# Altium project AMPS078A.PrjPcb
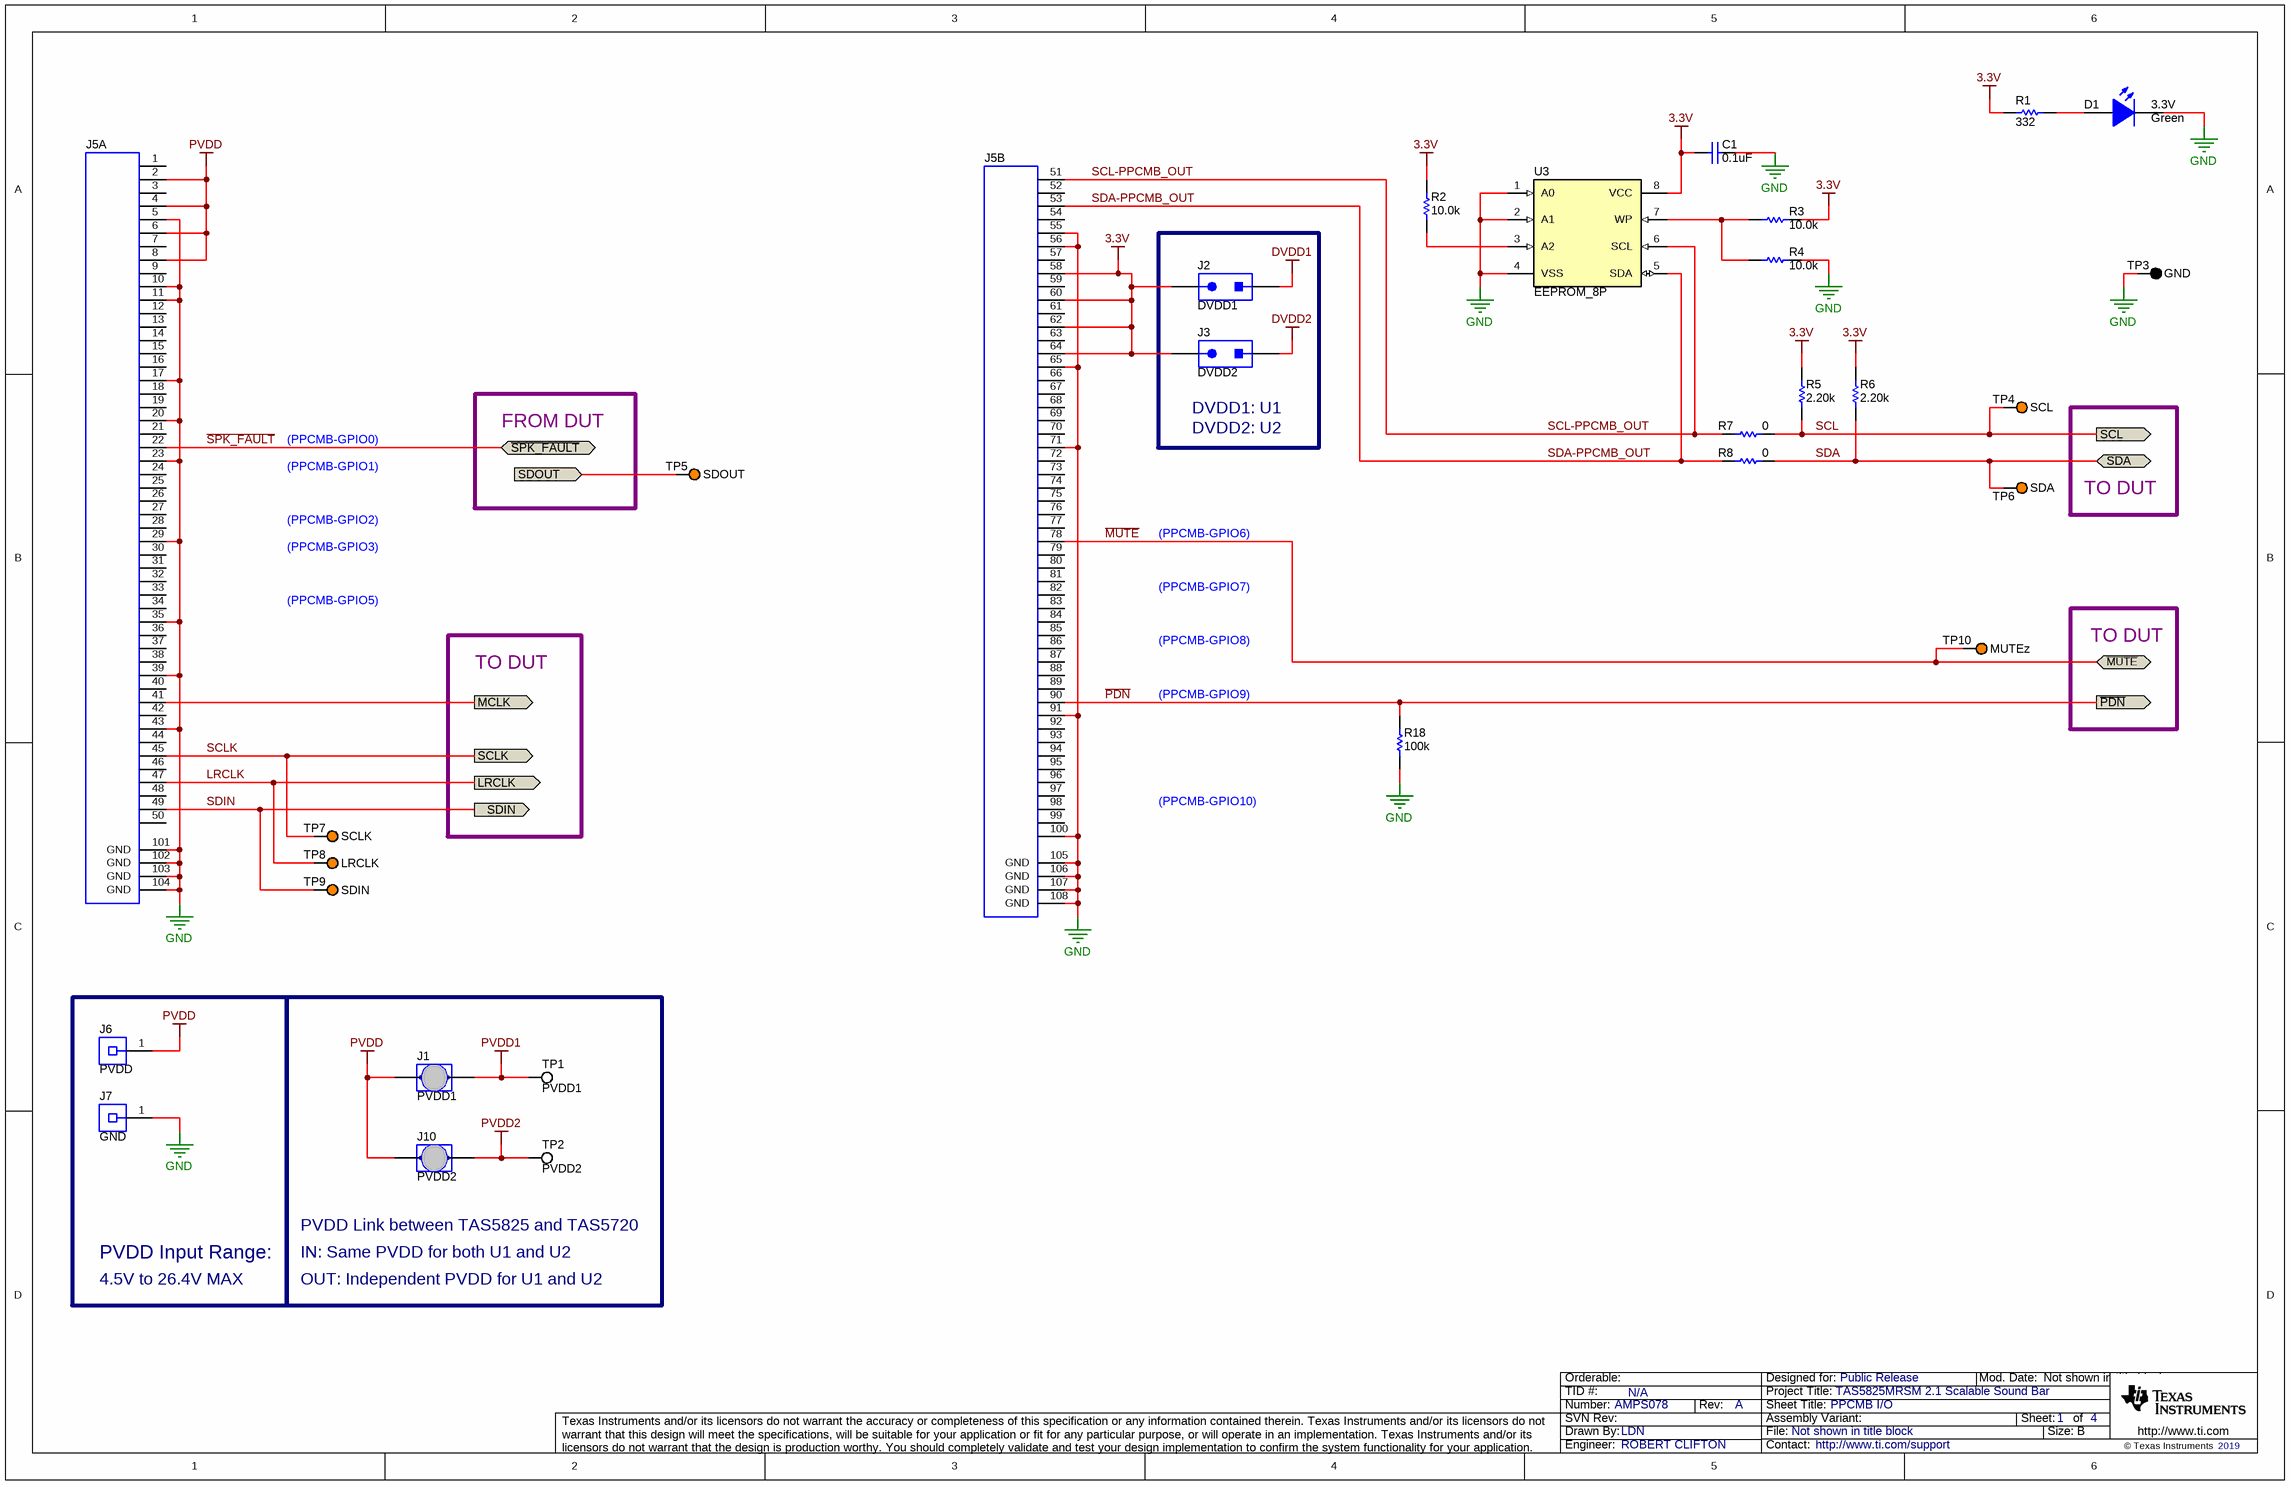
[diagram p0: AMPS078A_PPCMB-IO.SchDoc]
CopyrightYear: 2019; PCB_Layout: LDN; PCB_Rev: A; PRJ_Customer: Public Release; PRJ_Engineer: ROBERT CLIFTON; PRJ_Number: AMPS078; PRJ_Title: TAS5825MRSM 2.1 Scalable Sound Bar; SCH_Rev: A; TechSupport: http://www.ti.com/support; TID: N/A
4 sheets, 114 parts. Net scope: flat (ports and power ports of the same name join across sheets).
Board file: AMPS078A_PCB.PcbDoc
Sheets:
  AMPS078A_PPCMB-IO.SchDoc
  AMPS078A_TAS5720MRSM.SchDoc
  AMPS078A_TAS5825MRSM.SchDoc
  AMPS078A_Hardware.SchDoc

## Sheet AMPS078A_PPCMB-IO.SchDoc: PPCMB I/O
size 431 x 279 mm; Date: Not shown in title block; ApprovedBy: Not shown in title block; CheckedBy: Not shown in title block; Author: Not shown in title block; CompanyName: Not shown in title block; DrawnBy: LDN; Engineer: Not shown in title block; Organization: Not shown in title block; Address1: Not shown in title block; Address2: Not shown in title block; Address3: Not shown in title block; Address4: Not shown in title block; DocumentNumber: 1; Revision: Use project parameter SCH_Rev; SheetNumber: 1; SheetTotal: 4; PageSetup: Record=PageOptions¦CenterHorizontal=True¦CenterVertical=True¦PrintScale=1.00¦XCorrection=1.00¦YCorrection=1.00¦PrintKind=0¦BorderSize=5000000¦LeftOffset=0¦BottomOffset=0¦Orientation=2¦PaperLength=1000¦PaperWidth=1000¦Scale=100¦PaperSource=15¦PrintQuality=600¦MediaType=1¦DitherType=10¦PaperKind=Letter¦PrintScaleMode=1

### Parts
C1  ValueDisplayed: 0.1uF  [0603L]  (hidden comment: GRM188R71H104KA93D)
D1  3.3V  value Green  [LTST-C170KGKT_Green]
J1  PVDD1  [HARWIN_S1911-46R]
J2  DVDD1  [Sullins_PBC02SAAN]
J3  DVDD2  [Sullins_PBC02SAAN]
J5  QTS-050-01-F-D-A  [CONN_QTS-050-01-F-D-A]  (value not drawn)  (parts A,B of 2)
J6  PVDD  [Keystone_7006]
J7  GND  [Keystone_7007]
J10  PVDD2  [HARWIN_S1911-46R]
R1  ValueDisplayed: 332  [0402L]  (hidden comment: Resistor)
R2  ValueDisplayed: 10.0k  [0402L]  (hidden comment: Resistor)
R3  ValueDisplayed: 10.0k  [0402L]  (hidden comment: Resistor)
R4  ValueDisplayed: 10.0k  [0402L]  (hidden comment: Resistor)
R5  ValueDisplayed: 2.20k  [0402L]  (hidden comment: Resistor)
R6  ValueDisplayed: 2.20k  [0402L]  (hidden comment: Resistor)
R7  ValueDisplayed: 0  [0603L]  (hidden comment: Resistor)
R8  ValueDisplayed: 0  [0603L]  (hidden comment: Resistor)
R18  ValueDisplayed: 100k  [0402L]  (hidden comment: ERJ-2RKF1003X)
TP1  PVDD1  [Testpoint_Keystone_Compact]
TP2  PVDD2  [Testpoint_Keystone_Compact]
TP3  GND  [Keystone5001]
TP4  SCL  [Keystone5003]
TP5  SDOUT  [Keystone5003]
TP6  SDA  [Keystone5003]
TP7  SCLK  [Keystone5003]
TP8  LRCLK  [Keystone5003]
TP9  SDIN  [Keystone5003]
TP10  MUTEz  [Keystone5003]
U3  EEPROM_8P  [TSSOP-8]

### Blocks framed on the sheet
PVDD Input Range:: J6 J7

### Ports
LRCLK (out), MCLK (out), SCL (out), SCLK (out), SDA (bidir), SDIN (out), SDOUT (in), ~{MUTE} (bidir), ~{PDN} (out), ~{SPK_FAULT} (bidir)

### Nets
3.3V: C1.1 J2.2 J3.2 J5.58 J5.60 J5.62 J5.64 R1.2 R2.2 R3.1 R5.2 R6.2 U3.8(VCC)
DVDD1: J2.1
DVDD2: J3.1
GND: C1.2 D1.2(K) J5.5 J5.10 J5.11 J5.17 J5.20 J5.23 J5.29 J5.35 J5.39 J5.43 J5.55 J5.56 J5.65 J5.71 J5.91 J5.100 J5.101(GND) J5.102(GND) J5.103(GND) J5.104(GND) J5.105(GND) J5.106(GND) J5.107(GND) J5.108(GND) J7.1 R4.1 R18.1 TP3.1 U3.1(A0) U3.2(A1) U3.4(VSS)
PVDD: J1.1 J5.2 J5.4 J5.6 J5.8 J6.1 J10.1
PVDD1: J1.2 TP1.1
PVDD2: J10.2 TP2.1
~{MUTE}: J5.78 TP10.1 ; port ~{MUTE}
~{PDN}: J5.90 R18.2 ; port ~{PDN}
~{SPK_FAULT}: J5.22 ; port ~{SPK_FAULT}
LRCLK: J5.47 TP8.1 ; port LRCLK
MCLK: J5.41 ; port MCLK
SCL: R5.1 R7.1 TP4.1 ; port SCL
SCL-PPCMB_OUT: J5.51 R7.2 U3.6(SCL)
SCLK: J5.45 TP7.1 ; port SCLK
SDA: R6.1 R8.1 TP6.1 ; port SDA
SDA-PPCMB_OUT: J5.53 R8.2 U3.5(SDA)
SDIN: J5.49 TP9.1 ; port SDIN
SDOUT: TP5.1 ; port SDOUT
NetD1_1: D1.1(A) R1.1
NetR2_1: R2.1 U3.3(A2)
NetR3_2: R3.2 R4.2 U3.7(WP)

Not connected (* = marked no-connect by the designer): J5 1 3 7 9 12 13 14 15 16 18 19 21 24 25 26 27 28 30 31 32 33 34 36 37 38 40 42 44 46 48 50 52(2) 54(4) 57(7) 59(9) 61(11) 63(13) 66(16) 67(17) 68(18) 69(19) 70(20) 72(22) 73(23) 74(24) 75(25) 76(26) 77(27) 79(29) 80(30) 81(31) 82(32) 83(33) 84(34) 85(35) 86(36) 87(37) 88(38) 89(39) 92(42) 93(43) 94(44) 95(45) 96(46) 97(47) 98(48) 99(49)

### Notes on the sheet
- FROM DUT
- (near J3) DVDD1: U1
- DVDD2: U2
- (PPCMB-GPIO0)
- (PPCMB-GPIO1)
- TO DUT
- (PPCMB-GPIO3)
- (PPCMB-GPIO2)
- (PPCMB-GPIO6)
- (PPCMB-GPIO5)
- (PPCMB-GPIO7)
- (PPCMB-GPIO8)
- (PPCMB-GPIO9)
- (PPCMB-GPIO10)
- PVDD Link between TAS5825 and TAS5720
- 4.5V to 26.4V MAX
- IN: Same PVDD for both U1 and U2
- OUT: Independent PVDD for U1 and U2

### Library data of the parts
C1 = CMP-0007434-4: CAP, CERM, 0.1 uF, 50 V, +/- 10%, X7R, 0603; Manufacturer: MuRata; TaMin_C: -55°C; Polarized: N; SizeAreaWB_mm2: 4.68; Value1: Unknown; U/M: EA; Value: 0.1uF; TaMax_C: 125°C; SizeZ_mm: 1; SizeX_mm: 1.6; SizeY_mm: 0.8; Cap_Case: 0603; Value2: 50V; SizeArea_mm2: 1.28; CompType: Capacitor; Cap_F: 100nF; AEC Category: Q200
D1 = CMP-0002888-1: LED, Green, SMD; Manufacturer: Lite-On; PartNumber: LTST-C170KGKT; Type: AlInGaP; Vf_V: 2V; Io_A: 20mA; Value1: W; U/M: EA
J1 J10 = CMP-0075020-1: JUMPER TIN SMD; Manufacturer: Harwin; PartNumber: S1911-46R; CNHeader: False; Green_Lifecycle: Active; Green_REACh: Passed; CompType: Jumper SMT
J2 J3 = CMP-0054566-1: Header, 100mil, 2x1, Gold, TH; Manufacturer: Sullins Connector Solutions; PartNumber: PBC02SAAN; CNHeader: TRUE; Current_A: 3A; Green_Lifecycle: Active; Shrouded: N; Gender: Male; Green_REACh: Passed; Voltage_V: 1.8kV; Row_Count: 1; Pitch_mm: 2.54; CT: FALSE; Cert_UL: Y
J5 = CMP-0055971-1: Connector, 100 Pos. 0.635mm, SMT; Manufacturer: Samtec; CNHeader: FALSE; Green_Lifecycle: Active; Green_REACh: Passed
J6 = CMP-0055127-1: Binding Post, RED, TH; Manufacturer: Keystone; PartNumber: 7006; CNHeader: FALSE; Green_Lifecycle: Active; Green_REACh: Passed; CompType: Connector
J7 = CMP-0055128-1: Binding Post, BLACK, TH; Manufacturer: Keystone; PartNumber: 7007; CNHeader: FALSE; Green_Lifecycle: Active; Green_REACh: Passed; CompType: Connector
R1 = CMP-0026297-2: RES, 332, 1%, 0.063 W, AEC-Q200 Grade 0, 0402; PartNumber: CRCW0402332RFKED; Manufacturer: Vishay-Dale; Value: 332; Value_Code: 332R; Power_W: 63mW; Value2: 0.063W; VDC_V: 50V; TempCo: 100 ppm/C; EIA_Code: E96; AEC Category: Q200; AEC Qualified: Y; AEC Grade: 0; SizeArea_mm2: 0.5; SizeX_mm: 1; SizeZ_mm: 0.6
R2-R4 = CMP-0025958-3: RES, 10.0 k, 1%, 0.063 W, AEC-Q200 Grade 0, 0402; PartNumber: CRCW040210K0FKED; Manufacturer: Vishay-Dale; Value: 10.0k; Res_ohm: 10k; Value_Code: 10k0; Power_W: 63mW; Value2: 0.063W; VDC_V: 50V; TempCo: 100 ppm/C; EIA_Code: E96; AEC Category: Q200; AEC Qualified: Y; AEC Grade: 0; SizeArea_mm2: 0.5; SizeX_mm: 1; SizeZ_mm: 0.6
R5 R6 = CMP-0026231-2: RES, 2.20 k, 1%, 0.063 W, AEC-Q200 Grade 0, 0402; PartNumber: CRCW04022K20FKED; Manufacturer: Vishay-Dale; Value: 2.20k; Res_ohm: 2.2k; Value_Code: 2k20; Power_W: 63mW; Value2: 0.063W; TempCo: 100 ppm/C; AEC Category: Q200; AEC Qualified: Y; AEC Grade: 0; SizeArea_mm2: 0.5; SizeX_mm: 1; SizeZ_mm: 0.6
R7 R8 = CMP-0025697-4: RES, 0, 5%, 0.1 W, AEC-Q200 Grade 0, 0603; PartNumber: CRCW06030000Z0EA; Manufacturer: Vishay-Dale; Value: 0; Value_Code: 0000; Power_W: 100mW; Value2: 0.1W; VDC_V: 75V; TempCo: 200 ppm/C; EIA_Code: E24; AEC Category: Q200; AEC Qualified: Y; SizeArea_mm2: 1.28; SizeX_mm: 1.6; SizeY_mm: 0.8; SizeZ_mm: 1
R18 = CMP-0026659-1: RES, 100 k, 1%, 0.1 W, 0402; Manufacturer: Panasonic; Power_W: 100mW; TempCo: 100 ppm/C; U/M: EA; Value: 100k; EIA_Code: E96; SizeX_mm: 1; SizeY_mm: 0.5; SizeZ_mm: 0.6; Value2: 0.1W; CompType: Resistor; VDC_V: 50V; AEC Category: Q200
TP1 TP2 = CMP-0055153-1: Test Point, Compact, SMT; Manufacturer: Keystone; PartNumber: 5016; CNHeader: FALSE; Green_Lifecycle: Active; Green_REACh: Passed; CT: TRUE
TP3 = CMP-0055138-1: Test Point, Miniature, Black, TH; Manufacturer: Keystone; ContactFinish: Silver; CNHeader: FALSE; CT: TRUE; Green_Lifecycle: Active; Green_REACh: Passed
TP4-TP9 = CMP-0055140-1: Test Point, Miniature, Orange, TH; PartNumber: 5003; Manufacturer: Keystone; ContactFinish: Silver; CNHeader: FALSE; CT: TRUE; Green_Lifecycle: Active; Green_REACh: Passed
TP10 = CMP-0055140-1: Test Point, Miniature, Orange, TH; Manufacturer: Keystone; PartNumber: 5003; CNHeader: FALSE; Green_Lifecycle: Active; Green_REACh: Passed; ContactFinish: Silver; CT: TRUE
U3 = CMP-0005242-2: EEPROM, 512KBIT, 400KHZ, 8TSSOP; PartNumber: 24LC512-I/ST; Manufacturer: Microchip; SizeAreaWB_mm2: 42; SizeArea_mm2: 19.2; SizeX_mm: 6.4; SizeY_mm: 3; SizeZ_mm: 1.2

## Sheet AMPS078A_TAS5720MRSM.SchDoc: TAS5720MRSM I/O
size 323 x 209 mm; Date: Not shown in title block; ApprovedBy: Not shown in title block; CheckedBy: Not shown in title block; Author: Not shown in title block; CompanyName: Not shown in title block; DrawnBy: LDN; Engineer: Not shown in title block; Organization: Not shown in title block; Address1: Not shown in title block; Address2: Not shown in title block; Address3: Not shown in title block; Address4: Not shown in title block; DocumentNumber: 2; Revision: Use project parameter SCH_Rev; SheetNumber: 2; SheetTotal: 4; PageSetup: Record=PageOptions¦CenterHorizontal=True¦CenterVertical=True¦PrintScale=1.00¦XCorrection=1.00¦YCorrection=1.00¦PrintKind=0¦BorderSize=5000000¦LeftOffset=0¦BottomOffset=0¦Orientation=2¦PaperLength=1000¦PaperWidth=1000¦Scale=100¦PaperSource=15¦PrintQuality=600¦MediaType=1¦DitherType=10¦PaperKind=Letter¦PrintScaleMode=1
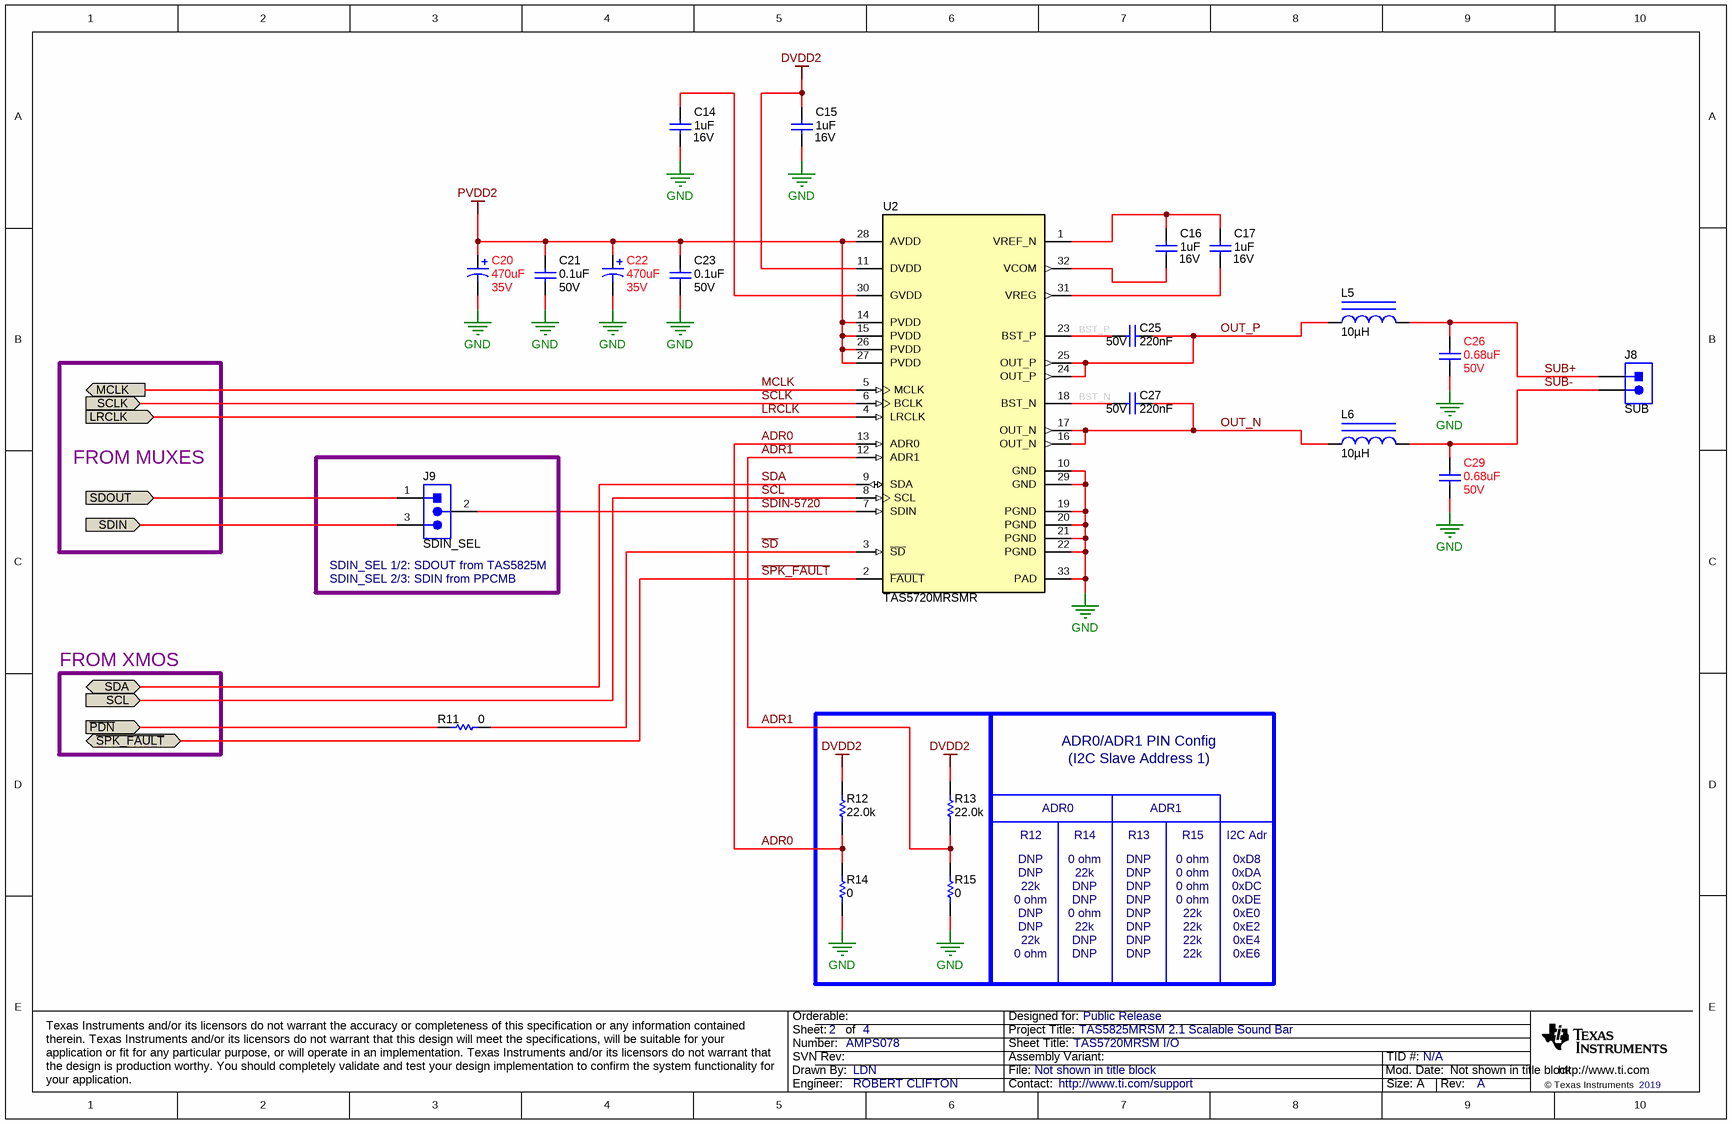
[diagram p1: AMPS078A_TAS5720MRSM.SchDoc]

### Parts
C14  VDC_V: 16V  ValueDisplayed: 1uF  [0603L]  (hidden comment: GRM188R71C105KA12D)
C15  VDC_V: 16V  ValueDisplayed: 1uF  [0603L]  (hidden comment: GRM188R71C105KA12D)
C16  VDC_V: 16V  ValueDisplayed: 1uF  [0603L]  (hidden comment: GRM188R71C105KA12D)
C17  VDC_V: 16V  ValueDisplayed: 1uF  [0603L]  (hidden comment: GRM188R71C105KA12D)
C20  VDC_V: 35V  ValueDisplayed: 470uF  [CAPSMT_62_KE0]  (hidden comment: +)
C21  VDC_V: 50V  ValueDisplayed: 0.1uF  [0603L]  (hidden comment: GRM188R71H104KA93D)
C22  VDC_V: 35V  ValueDisplayed: 470uF  [CAPSMT_62_KE0]  (hidden comment: +)
C23  VDC_V: 50V  ValueDisplayed: 0.1uF  [0603L]  (hidden comment: GRM188R71H104KA93D)
C25  Cap_F: 220nF  VDC_V: 50V  [0603L]  (hidden comment: GCM188R71H224KA64D)
C26  VDC_V: 50V  ValueDisplayed: 0.68uF  [0805_HV1]  (hidden comment: C2012X7R1H684M125AB)
C27  Cap_F: 220nF  VDC_V: 50V  [0603L]  (hidden comment: GCM188R71H224KA64D)
C29  VDC_V: 50V  ValueDisplayed: 0.68uF  [0805_HV1]  (hidden comment: C2012X7R1H684M125AB)
J8  SUB  [JST_B2PS-VH]
J9  SDIN_SEL  [PBC03SAAN]
L5  ValueDisplayed: 10µH  [DEM10050C]  (hidden comment: 1274AS-H-100M=P3)
L6  ValueDisplayed: 10µH  [DEM10050C]  (hidden comment: 1274AS-H-100M=P3)
R11  ValueDisplayed: 0  [0603L]  (hidden comment: CRCW06030000Z0EA)
R12  ValueDisplayed: 22.0k  [0603L]  (hidden comment: DNP)
R13  ValueDisplayed: 22.0k  [0603L]  (hidden comment: DNP)
R14  ValueDisplayed: 0  [0603L]  (hidden comment: CRCW06030000Z0EA)
R15  ValueDisplayed: 0  [0603L]  (hidden comment: CRCW06030000Z0EA)
U2  TAS5720MRSMR  [RSM0032B]

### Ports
LRCLK (in), MCLK (out), SCL (in), SCLK (in), SDA (bidir), SDIN (in), SDOUT (in), ~{PDN} (in), ~{SPK_FAULT} (bidir)

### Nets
DVDD2: C15.1 R12.2 R13.2 U2.11(DVDD)
GND: C14.2 C15.2 C20.2(-) C21.2 C22.2(-) C23.2 C26.2 C29.2 R14.1 R15.1 U2.10(GND) U2.19(PGND) U2.20(PGND) U2.21(PGND) U2.22(PGND) U2.29(GND) U2.33(PAD)
PVDD2: C20.1(+) C21.1 C22.1(+) C23.1 U2.14(PVDD) U2.15(PVDD) U2.26(PVDD) U2.27(PVDD) U2.28(AVDD)
~{PDN}: R11.2 ; port ~{PDN}
~{SD}: R11.1 U2.3(~{SD})
~{SPK_FAULT}: U2.2(~{FAULT}) ; port ~{SPK_FAULT}
ADR0: R12.1 R14.2 U2.13(ADR0)
ADR1: R13.1 R15.2 U2.12(ADR1)
BST_N: C27.1 U2.18(BST_N)
BST_P: C25.1 U2.23(BST_P)
LRCLK: U2.4(LRCLK) ; port LRCLK
MCLK: U2.5(MCLK) ; port MCLK
OUT_N: C27.2 L6.1 U2.16(OUT_N) U2.17(OUT_N)
OUT_P: C25.2 L5.1 U2.24(OUT_P) U2.25(OUT_P)
SCL: U2.8(SCL) ; port SCL
SCLK: U2.6(BCLK) ; port SCLK
SDA: U2.9(SDA) ; port SDA
SDIN: J9.3 ; port SDIN
SDIN-5720: J9.2 U2.7(SDIN)
SDOUT: J9.1 ; port SDOUT
SUB+: C26.1 J8.1 L5.2
SUB-: C29.1 J8.2 L6.2
NetC14_1: C14.1 U2.30(GVDD)
NetC16_1: C16.1 C17.1 U2.1(VREF_N)
NetC16_2: C16.2 U2.32(VCOM)
NetC17_2: C17.2 U2.31(VREG)

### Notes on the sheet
- FROM MUXES
- (near J9) SDIN_SEL 1/2: SDOUT from TAS5825M
- (near J9) SDIN_SEL 2/3: SDIN from PPCMB
- FROM XMOS
- ADR0/ADR1 PIN Config
- ADR0
- (I2C Slave Address 1)
- ADR1
- R12
- DNP
- R14
- 0 ohm
- 22k
- R13
- R15
- I2C Adr
- 0xD8
- 0xDA
- 0xDC
- 0xDE
- 0xE0
- 0xE2
- 0xE4
- 0xE6

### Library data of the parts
C14-C17 = CMP-0007379-4: CAP, CERM, 1 uF, 16 V, +/- 10%, X7R, 0603; Manufacturer: MuRata; TaMin_C: -55°C; ESR_ohm: 0.011; Polarized: N; SizeAreaWB_mm2: 4.68; Value1: 0.011 ohm; U/M: EA; Value: 1uF; TaMax_C: 125°C; SizeZ_mm: 1; SizeX_mm: 1.6; SizeY_mm: 0.8; Cap_Case: 0603; SizeArea_mm2: 1.28; CompType: Capacitor; Cap_F: 1µF; AEC Category: Q200
C20 C22 = CMP-0010879-1: CAP, AL, 470 uF, 35 V, +/- 20%, SMD; Manufacturer: Chemi-Con; PartNumber: EMVE350ATR471MKE0S; NewPartNumber: EMVE350ARA471MKE0S; TaMin_C: -40°C; Polarized: Y; SizeAreaWB_mm2: 225; Value1: Unknown; U/M: EA; Value: 470uF; TaMax_C: 105°C; SizeZ_mm: 13.5; SizeX_mm: 13; Cap_Case: KE0; SizeArea_mm2: 169; CompType: Capacitor; Cap_F: 470µF; IRMS_A: 5.2dA; AEC Category: Q200
C21 C23 = CMP-0007434-4: CAP, CERM, 0.1 uF, 50 V, +/- 10%, X7R, 0603; Manufacturer: MuRata; TaMin_C: -55°C; Polarized: N; SizeAreaWB_mm2: 4.68; Value1: Unknown; U/M: EA; Value: 0.1uF; TaMax_C: 125°C; SizeZ_mm: 1; SizeX_mm: 1.6; SizeY_mm: 0.8; Cap_Case: 0603; SizeArea_mm2: 1.28; CompType: Capacitor; Cap_F: 100nF; AEC Category: Q200
C25 C27 = CMP-0007145-4: CAP, CERM, 0.22 uF, 50 V, +/- 10%, X7R, AEC-Q200 Grade 1, 0603; Manufacturer: MuRata; TaMin_C: -55°C; Polarized: N; SizeAreaWB_mm2: 4.68; Value1: Unknown; U/M: EA; Value: 0.22uF; TaMax_C: 125°C; SizeZ_mm: 1; SizeX_mm: 1.6; SizeY_mm: 0.8; Cap_Case: 0603; SizeArea_mm2: 1.28; AEC Qualified: Y; AEC Category: Q200
C26 C29 = CMP-0007882-2: CAP, CERM, 0.68 uF, 50 V, +/- 20%, X7R, 0805; Manufacturer: TDK; NewPartNumber: CGA4J3X7R1H684M125AB; TaMin_C: -55°C; Polarized: N; SizeAreaWB_mm2: 6.75; Value1: Unknown; U/M: EA; Value: 0.68uF; TaMax_C: 125°C; SizeZ_mm: 1.45; SizeX_mm: 2; SizeY_mm: 1.25; Cap_Case: 0805; SizeArea_mm2: 2.5; CompType: Capacitor; Cap_F: 680nF; AEC Category: Q200
J8 = CMP-0074989-1: Header (friction lock), 3.96mm, 2x1, Tin, R/A, TH; Manufacturer: JST Manufacturing; PartNumber: B2PS-VH(LF)(SN); CNHeader: False; Green_Lifecycle: Active; Green_REACh: Passed
J9 = CMP-0002334-1: Header, 100mil, 3x1, Gold, TH; Manufacturer: Sullins Connector Solutions; CNHeader: TRUE; Green_Lifecycle: Not Set; Green_REACh: Incomplete; CT: FALSE
L5 L6 = CMP-0077807-1: Inductor, Shielded, Ferrite, 10 µH, 4.4 A, 0.0304 ohm, SMD; Manufacturer: MuRata; Isat: 6.2A @ 30% inductance drop; Irms: 4.4A @ 40C rise; SizeAreaWB_mm2: 144.0; DCR_ohm: 0.0304; Value: 10uH; Imax_A: 4.4A; SizeZ_mm: 5.0; SizeX_mm: 10.0; SizeArea_mm2: 100.0; AEC Qualified: N; AEC Category: Q200
R11 R14 R15 = CMP-0025697-4: RES, 0, 5%, 0.1 W, AEC-Q200 Grade 0, 0603; Manufacturer: Vishay-Dale; Power_W: 100mW; TempCo: 200 ppm/C; Value_Code: 0000; Value: 0; EIA_Code: E24; SizeX_mm: 1.6; SizeY_mm: 0.8; SizeZ_mm: 1; Value2: 0.1W; SizeArea_mm2: 1.28; CompType: Resistor; AEC Qualified: Y; VDC_V: 75V; AEC Category: Q200
R12 R13 = CMP-0022692-3: RES, 22.0 k, 1%, 0.1 W, AEC-Q200 Grade 0, 0603; Manufacturer: Panasonic; PartNumber: ERJ-3EKF2202V; Power_W: 100mW; TempCo: 100 ppm/C; Value_Code: 22k0; U/M: EA; Value: 22.0k; Res_ohm: 22k; SizeX_mm: 1.6; SizeY_mm: 0.8; SizeZ_mm: 1; Value2: 0.1W; SizeArea_mm2: 1.28; CompType: Resistor; AEC Qualified: Y; VDC_V: 50V; AEC Grade: 0; AEC Category: Q200
U2 = CMP-0075842-2: Closed Loop I2S Input Amplifier with Power Limiter, PVDDmax of 26.4V, RSM0032B (VQFN-32); Manufacturer: Texas Instruments; Alternate PartNumber: TAS5720MRSMT; SizeAreaWB_mm2: 25; SizeArea_mm2: 16; SizeZ_mm: 1; SizeY_mm: 4; CompType: IC; AEC Category: Q200; AEC Qualified: N

## Sheet AMPS078A_TAS5825MRSM.SchDoc: TAS5825MRSM I/O
size 323 x 209 mm; Date: Not shown in title block; ApprovedBy: Not shown in title block; CheckedBy: Not shown in title block; Author: Not shown in title block; CompanyName: Not shown in title block; DrawnBy: LDN; Engineer: Not shown in title block; Organization: Not shown in title block; Address1: Not shown in title block; Address2: Not shown in title block; Address3: Not shown in title block; Address4: Not shown in title block; DocumentNumber: 3; Revision: Use project parameter SCH_Rev; SheetNumber: 3; SheetTotal: 4; PageSetup: Record=PageOptions¦CenterHorizontal=True¦CenterVertical=True¦PrintScale=1.00¦XCorrection=1.00¦YCorrection=1.00¦PrintKind=0¦BorderSize=5000000¦LeftOffset=0¦BottomOffset=0¦Orientation=2¦PaperLength=1000¦PaperWidth=1000¦Scale=100¦PaperSource=15¦PrintQuality=600¦MediaType=1¦DitherType=10¦PaperKind=Letter¦PrintScaleMode=1
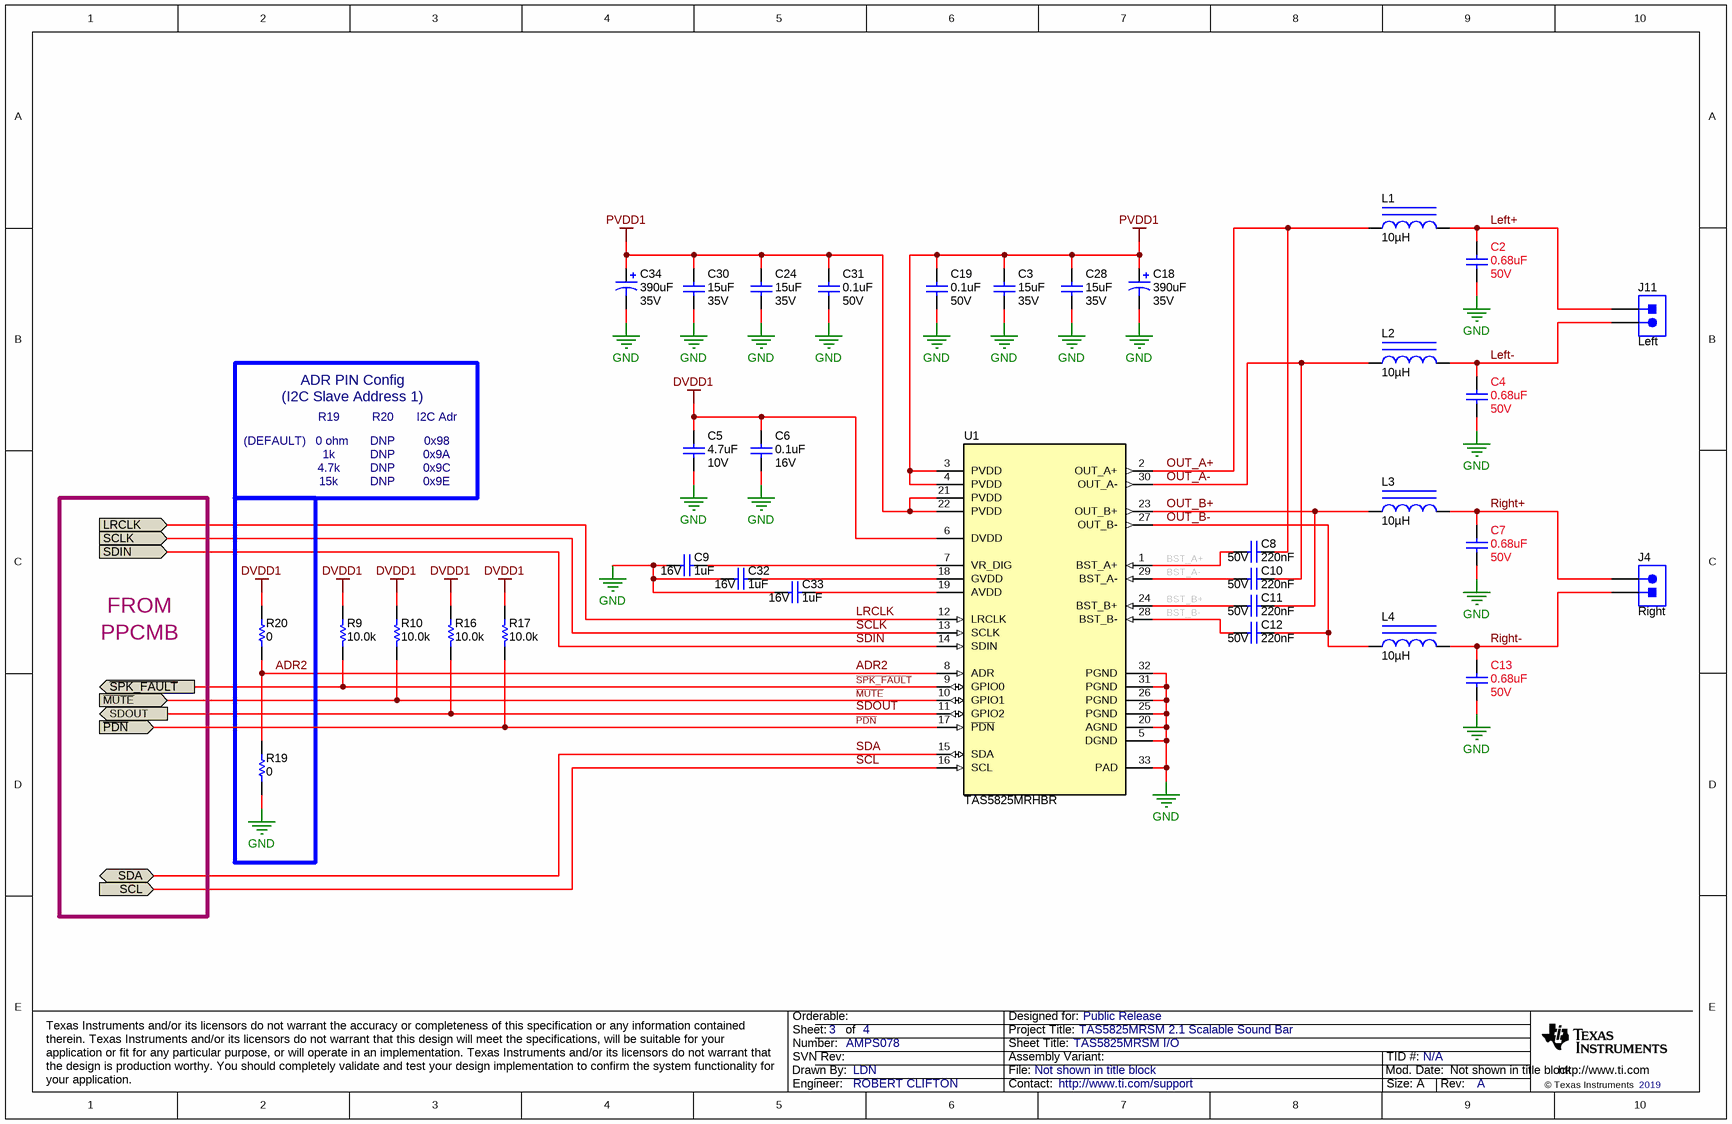
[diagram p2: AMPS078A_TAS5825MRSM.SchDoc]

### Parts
C2  VDC_V: 50V  ValueDisplayed: 0.68uF  [0805L]  (hidden comment: C0805C684K5RACTU)
C3  VDC_V: 35V  ValueDisplayed: 15uF  [0805L]  (hidden comment: C2012X5R1V156M125AC)
C4  VDC_V: 50V  ValueDisplayed: 0.68uF  [0805L]  (hidden comment: C0805C684K5RACTU)
C5  VDC_V: 10V  ValueDisplayed: 4.7uF  [0603L]  (hidden comment: C0603C475K8PACTU)
C6  VDC_V: 16V  ValueDisplayed: 0.1uF  [0603L]  (hidden comment: C0603C104K4RACTU)
C7  VDC_V: 50V  ValueDisplayed: 0.68uF  [0805L]  (hidden comment: C0805C684K5RACTU)
C8  Cap_F: 220nF  VDC_V: 50V  [0603L]  (hidden comment: GCM188R71H224KA64D)
C9  VDC_V: 16V  ValueDisplayed: 1uF  [0603L]  (hidden comment: C0603C105K4PACTU)
C10  Cap_F: 220nF  VDC_V: 50V  [0603L]  (hidden comment: GCM188R71H224KA64D)
C11  Cap_F: 220nF  VDC_V: 50V  [0603L]  (hidden comment: GCM188R71H224KA64D)
C12  Cap_F: 220nF  VDC_V: 50V  [0603L]  (hidden comment: GCM188R71H224KA64D)
C13  VDC_V: 50V  ValueDisplayed: 0.68uF  [0805L]  (hidden comment: C0805C684K5RACTU)
C18  VDC_V: 35V  ValueDisplayed: 390uF  [SM_RADIAL_10BMM]  (hidden comment: +)
C19  VDC_V: 50V  ValueDisplayed: 0.1uF  [0402L]  (hidden comment: CGA2B3X7R1H104K050BB)
C24  VDC_V: 35V  ValueDisplayed: 15uF  [0805L]  (hidden comment: C2012X5R1V156M125AC)
C28  VDC_V: 35V  ValueDisplayed: 15uF  [0805L]  (hidden comment: C2012X5R1V156M125AC)
C30  VDC_V: 35V  ValueDisplayed: 15uF  [0805L]  (hidden comment: C2012X5R1V156M125AC)
C31  VDC_V: 50V  ValueDisplayed: 0.1uF  [0402L]  (hidden comment: CGA2B3X7R1H104K050BB)
C32  VDC_V: 16V  ValueDisplayed: 1uF  [0603L]  (hidden comment: C0603C105K4PACTU)
C33  VDC_V: 16V  ValueDisplayed: 1uF  [0603L]  (hidden comment: C0603C105K4PACTU)
C34  VDC_V: 35V  ValueDisplayed: 390uF  [SM_RADIAL_10BMM]  (hidden comment: +)
J4  Right  [JST_B2PS-VH]
J11  Left  [JST_B2PS-VH]
L1  ValueDisplayed: 10µH  [DEM10050C]  (hidden comment: 1274AS-H-100M=P3)
L2  ValueDisplayed: 10µH  [DEM10050C]  (hidden comment: 1274AS-H-100M=P3)
L3  ValueDisplayed: 10µH  [DEM10050C]  (hidden comment: 1274AS-H-100M=P3)
L4  ValueDisplayed: 10µH  [DEM10050C]  (hidden comment: 1274AS-H-100M=P3)
R9  ValueDisplayed: 10.0k  [0402L]  (hidden comment: RMCF0402FT10K0)
R10  ValueDisplayed: 10.0k  [0402L]  (hidden comment: RMCF0402FT10K0)
R16  ValueDisplayed: 10.0k  [0402L]  (hidden comment: RMCF0402FT10K0)
R17  ValueDisplayed: 10.0k  [0402L]  (hidden comment: RMCF0402FT10K0)
R19  ValueDisplayed: 0  [0402L]  (hidden comment: ERJ-2GE0R00X)
R20  ValueDisplayed: 0  [0402L]  (hidden comment: DNP)
U1  TAS5825MRHBR  [RHB0032N]

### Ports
LRCLK (in), SCL (in), SCLK (in), SDA (bidir), SDIN (in), SDOUT (out), ~{MUTE} (in), ~{PDN} (in), ~{SPK_FAULT} (out)

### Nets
DVDD1: C5.2 C6.1 R9.2 R10.2 R16.2 R17.2 R20.2 U1.6(DVDD)
GND: C2.2 C3.1 C4.2 C5.1 C6.2 C7.2 C9.2 C13.2 C18.2(-) C19.2 C24.1 C28.1 C30.1 C31.2 C32.2 C33.2 C34.2(-) R19.2 U1.5(DGND) U1.20(AGND) U1.25(PGND) U1.26(PGND) U1.31(PGND) U1.32(PGND) U1.33(PAD)
PVDD1: C3.2 C18.1(+) C19.1 C24.2 C28.2 C30.2 C31.1 C34.1(+) U1.3(PVDD) U1.4(PVDD) U1.21(PVDD) U1.22(PVDD)
~{MUTE}: R10.1 U1.10(GPIO1) ; port ~{MUTE}
~{PDN}: R17.1 U1.17(~{PDN}) ; port ~{PDN}
~{SPK_FAULT}: R9.1 U1.9(GPIO0) ; port ~{SPK_FAULT}
ADR2: R19.1 R20.1 U1.8(ADR)
BST_A+: C8.1 U1.1(BST_A+)
BST_A-: C10.1 U1.29(BST_A-)
BST_B+: C11.1 U1.24(BST_B+)
BST_B-: C12.1 U1.28(BST_B-)
Left+: C2.1 J11.1 L1.2
Left-: C4.1 J11.2 L2.2
LRCLK: U1.12(LRCLK) ; port LRCLK
OUT_A+: C8.2 L1.1 U1.2(OUT_A+)
OUT_A-: C10.2 L2.1 U1.30(OUT_A-)
OUT_B+: C11.2 L3.1 U1.23(OUT_B+)
OUT_B-: C12.2 L4.1 U1.27(OUT_B-)
Right+: C7.1 J4.2 L3.2
Right-: C13.1 J4.1 L4.2
SCL: U1.16(SCL) ; port SCL
SCLK: U1.13(SCLK) ; port SCLK
SDA: U1.15(SDA) ; port SDA
SDIN: U1.14(SDIN) ; port SDIN
SDOUT: R16.1 U1.11(GPIO2) ; port SDOUT
NetC9_1: C9.1 U1.7(VR_DIG)
NetC32_1: C32.1 U1.18(GVDD)
NetC33_1: C33.1 U1.19(AVDD)

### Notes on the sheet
- (I2C Slave Address 1)
- ADR PIN Config
- (DEFAULT)
- R19
- 1k
- 4.7k
- 0 ohm
- R20
- DNP
- I2C Adr
- 0x98
- 0x9A
- 0x9C
- 15k
- 0x9E
- FROM
- PPCMB

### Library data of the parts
C2 C4 C7 C13 = CMP-0007814-2: CAP, CERM, 0.68 uF, 50 V, +/- 10%, X7R, 0805; Manufacturer: Kemet; NewPartNumber: CGA4J3X7R1H684M125AB; TaMin_C: -55°C; Polarized: N; SizeAreaWB_mm2: 6.75; Value1: Unknown; U/M: EA; Value: 0.68uF; TaMax_C: 125°C; SizeZ_mm: 1.45; SizeX_mm: 2; SizeY_mm: 1.25; Cap_Case: 0805; SizeArea_mm2: 2.5; CompType: Capacitor; Cap_F: 680nF; AEC Category: Q200
C3 C24 C28 C30 = CMP-0007843-2: CAP, CERM, 15 uF, 35 V, +/- 20%, X5R, 0805; Manufacturer: TDK; TaMin_C: -55°C; ESR_ohm: 1.669m; Polarized: N; SizeAreaWB_mm2: 6.75; Value1: 0.001669 ohm; U/M: EA; Value: 15uF; TaMax_C: 85°C; SizeZ_mm: 1.45; SizeX_mm: 2; SizeY_mm: 1.25; Cap_Case: 0805; SizeArea_mm2: 2.5; Cap_F: 15µF; IRMS_A: 5.04984A; AEC Category: Q200
C5 = CMP-0006949-5: CAP, CERM, 4.7 uF, 10 V, +/- 10%, X5R, 0603; Manufacturer: Kemet; TaMin_C: -55°C; ESR_ohm: 6m; Polarized: N; SizeAreaWB_mm2: 4.68; Value1: 0.006 ohm; U/M: EA; Value: 4.7uF; TaMax_C: 85°C; SizeZ_mm: 1; SizeX_mm: 1.6; SizeY_mm: 0.8; Cap_Case: 0603; SizeArea_mm2: 1.28; CompType: Capacitor; Cap_F: 4.7µF; IRMS_A: 7.24A; AEC Category: Q200
C6 = CMP-0006860-5: CAP, CERM, 0.1 uF, 16 V, +/- 10%, X7R, 0603; Manufacturer: Kemet; TaMin_C: -55°C; Polarized: N; SizeAreaWB_mm2: 4.68; Value1: Unknown; U/M: EA; Value: 0.1uF; TaMax_C: 125°C; SizeZ_mm: 1; SizeX_mm: 1.6; SizeY_mm: 0.8; Cap_Case: 0603; SizeArea_mm2: 1.28; CompType: Capacitor; Cap_F: 100nF; AEC Category: Q200
C8 C10-C12 = CMP-0007145-4: as C25 on sheet AMPS078A_TAS5720MRSM
C9 C32 C33 = CMP-0006868-5: CAP, CERM, 1 uF, 16 V, +/- 10%, X5R, 0603; Manufacturer: Kemet; TaMin_C: -55°C; Polarized: N; SizeAreaWB_mm2: 4.68; Value1: Unknown; U/M: EA; Value: 1uF; TaMax_C: 85°C; SizeZ_mm: 1; SizeX_mm: 1.6; SizeY_mm: 0.8; Cap_Case: 0603; SizeArea_mm2: 1.28; CompType: Capacitor; Cap_F: 1µF; AEC Category: Q200
C18 C34 = CMP-0011092-1: CAP, AL, 390 uF, 35 V, +/- 20%, 0.08 ohm, SMD; Manufacturer: Nichicon; PartNumber: UCL1V391MNL1GS; TaMin_C: -55°C; ESR_ohm: 0.08; Polarized: Y; SizeAreaWB_mm2: 159.9; U/M: EA; Value: 390uF; TaMax_C: 105°C; SizeZ_mm: 10.2; SizeX_mm: 11; SizeY_mm: 10.3; Cap_Case: 10x10; SizeArea_mm2: 113.3; CompType: Capacitor; Cap_F: 390µF; IRMS_A: 8.5dA; AEC Category: Q200
C19 C31 = CMP-0006325-2: CAP, CERM, 0.1 uF, 50 V, +/- 10%, X7R, AEC-Q200 Grade 1, 0402; Manufacturer: TDK; TaMin_C: -55°C; ESR_ohm: 0.039064; Polarized: N; SizeAreaWB_mm2: 3; Value1: 0.039064 ohm; U/M: EA; Value: 0.1uF; TaMax_C: 125°C; SizeZ_mm: 0.6; SizeX_mm: 1; SizeY_mm: 0.5; Cap_Case: 0402; AEC Qualified: Y; Cap_F: 100nF; IRMS_A: 814.669mA; AEC Category: Q200
J4 J11 = CMP-0074989-1: as J8 on sheet AMPS078A_TAS5720MRSM
L1-L4 = CMP-0077807-1: as L5 on sheet AMPS078A_TAS5720MRSM
R9 R10 R16 R17 = CMP-0026754-1: RES, 10.0 k, 1%, 0.063 W, AEC-Q200 Grade 0, 0402; Manufacturer: Stackpole Electronics Inc; Power_W: 63mW; TempCo: 100 ppm/C; Value_Code: 10k0; U/M: EA; Value: 10.0k; EIA_Code: E96; Res_ohm: 10k; SizeX_mm: 1; SizeY_mm: 0.5; SizeZ_mm: 0.6; Value2: 0.063W; CompType: Resistor; AEC Qualified: Y; VDC_V: 50V; AEC Grade: 0; AEC Category: Q200
R19 = CMP-0026992-3: RES, 0, 5%, 0.1 W, AEC-Q200 Grade 0, 0402; Manufacturer: Panasonic; Power_W: 100mW; TempCo: 600 ppm/C; Value_Code: 0000; Value: 0; EIA_Code: E24; SizeX_mm: 1; SizeY_mm: 0.5; SizeZ_mm: 0.6; Value2: 0.1W; AEC Qualified: Y; VDC_V: 50V; AEC Category: Q200; SizeAreaWB_mm2: 3
R20 = CMP-0026992-3: RES, 0, 5%, 0.1 W, AEC-Q200 Grade 0, 0402; Manufacturer: Panasonic; PartNumber: ERJ-2GE0R00X; Power_W: 100mW; TempCo: 600 ppm/C; Value_Code: 0000; Value: 0; EIA_Code: E24; SizeX_mm: 1; SizeY_mm: 0.5; SizeZ_mm: 0.6; Value2: 0.1W; AEC Qualified: Y; VDC_V: 50V; AEC Category: Q200; SizeAreaWB_mm2: 3
U1 = CMP-0077820-2: 4.5 V to 26.4 V, Inductor-Less, Digital Input, Stereo, Closed-Loop Class-D Audio Amplifier with 96-kHz/192-kHz Extended Audio Processing, RHB0032N (VQFN-32); Alternate PartNumber: TAS5825MRHBT; Alternate Manufacturer: Texas Instruments; SizeAreaWB_mm2: 49.0; SizeZ_mm: 0.9; SizeX_mm: 5.0; SizeArea_mm2: 25.0; CompType: IC; AEC Qualified: N; AEC Category: Q200

## Sheet AMPS078A_Hardware.SchDoc: HARDWARE
size Letter; Date: Not shown in title block; ApprovedBy: Not shown in title block; CheckedBy: Not shown in title block; Author: Not shown in title block; CompanyName: Not shown in title block; DrawnBy: LDN; Engineer: Not shown in title block; Organization: Not shown in title block; Address1: Not shown in title block; Address2: Not shown in title block; Address3: Not shown in title block; Address4: Not shown in title block; DocumentNumber: 4; Revision: Use project parameter SCH_Rev; SheetNumber: 4; SheetTotal: 4; PageSetup: Record=PageOptions¦CenterHorizontal=True¦CenterVertical=True¦PrintScale=1.00¦XCorrection=1.00¦YCorrection=1.00¦PrintKind=0¦BorderSize=5000000¦LeftOffset=0¦BottomOffset=0¦Orientation=2¦PaperLength=1000¦PaperWidth=1000¦Scale=100¦PaperSource=15¦PrintQuality=600¦MediaType=1¦DitherType=10¦PaperKind=Letter¦PrintScaleMode=1
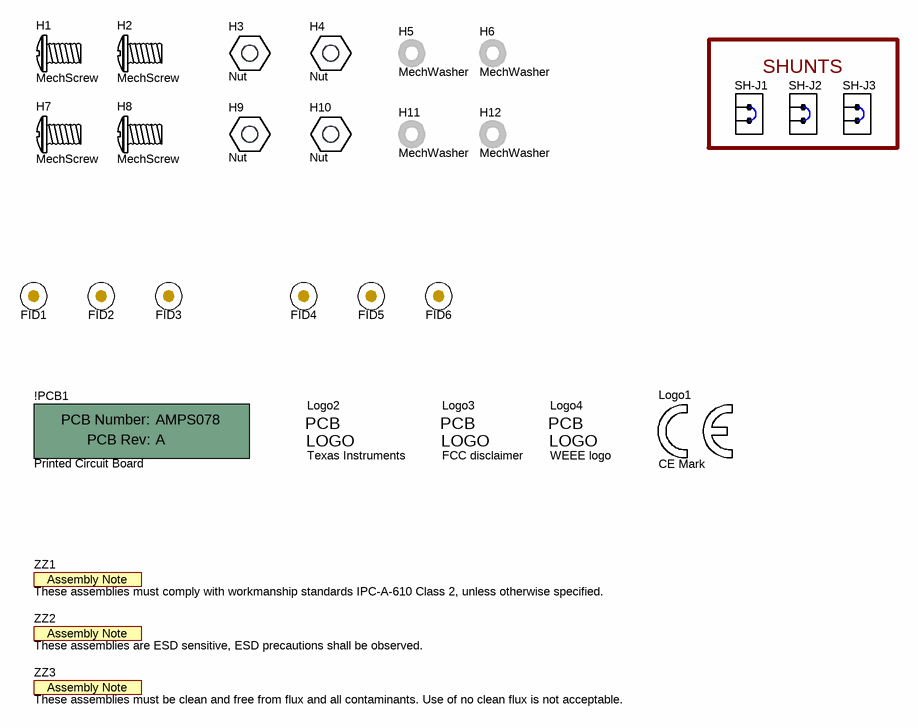
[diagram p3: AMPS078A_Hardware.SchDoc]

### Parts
!PCB1  Printed Circuit Board  (mechanical)
FID1  Fiducial  [Fiducial6.4-20]  (value not drawn)
FID2  Fiducial  [Fiducial6.4-20]  (value not drawn)
FID3  Fiducial  [Fiducial6.4-20]  (value not drawn)
FID4  Fiducial  [Fiducial6.4-20]  (value not drawn)
FID5  Fiducial  [Fiducial6.4-20]  (value not drawn)
FID6  Fiducial  [Fiducial6.4-20]  (value not drawn)
H1  MechScrew  [APM_RM3X8MM 2701]  (mechanical)
H2  MechScrew  [APM_RM3X8MM 2701]  (mechanical)
H3  Nut  [Harwin_R30-1003002]
H4  Nut  [Harwin_R30-1003002]
H5  MechWasher  (mechanical)
H6  MechWasher  (mechanical)
H7  MechScrew  [APM_RM3X8MM 2701]  (mechanical)
H8  MechScrew  [APM_RM3X8MM 2701]  (mechanical)
H9  Nut  [Harwin_R30-1003002]
H10  Nut  [Harwin_R30-1003002]
H11  MechWasher  (mechanical)
H12  MechWasher  (mechanical)
Logo1  CE Mark  [CE_Mark_5mm]  (no BOM)
Logo2  Texas Instruments  [TI_Stacked_Overlay_Small]  (no BOM)
Logo3  FCC disclaimer  [FCC_disclaimer_stacked]  (no BOM)
Logo4  WEEE logo  [WEEE_Minimum]  (no BOM)
SH-J1  SNT-100-BK-G  [SNT-100-BK-G]  (value not drawn)
SH-J2  SNT-100-BK-G  [SNT-100-BK-G]  (value not drawn)
SH-J3  SNT-100-BK-G  [SNT-100-BK-G]  (value not drawn)
ZZ1  These assemblies must comply with workmanship standards IPC-A-610 Class 2, unless otherwise specified.  [AssemblyNote]  (no BOM)
ZZ2  These assemblies are ESD sensitive, ESD precautions shall be observed.  [AssemblyNote]  (no BOM)
ZZ3  These assemblies must be clean and free from flux and all contaminants. Use of no clean flux is not acceptable.  [AssemblyNote]  (no BOM)

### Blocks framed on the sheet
SHUNTS: SH-J1-SH-J3

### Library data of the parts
!PCB1 = CMP-0003618-2: PartNumber: AMPS078; Manufacturer: Any
FID1-FID6 = CMP-0077181-1: Fiducial mark.  There is nothing to buy or mount.
H1 H2 H7 H8 = CMP-0003717-1: MACHINE SCREW PAN PHILLIPS M3; Manufacturer: APM HEXSEAL; PartNumber: RM3X8MM 2701; CompType: Standoff
H3 H4 H9 H10 = CMP-0003674-1: Standoff, HexBrass M3, 30 mm; Manufacturer: Harwin; PartNumber: R30-1003002; CompType: Spacer
H5 H6 H11 H12 = CMP-0003675-1: Washer, Flat, #4 Nylon; Manufacturer: Keystone; PartNumber: 3200
Logo1 = CMP-0074844-1: SymbolCreator: a0412235
Logo2 = CMP-0074838-1: Texas Instrument Corporate Signature; Library Reference: Logo; SymbolCreator: a0412235; Lib Reference: TI_Logo
Logo3 = CMP-0074847-1: FCC_disclaimer; Library Reference: Logo
Logo4 = CMP-0074769-1
SH-J1-SH-J3 = CMP-0003623-3: Shunt, 100mil, Gold plated, Black; Alternate PartNumber: 969102-0000-DA; Manufacturer: Samtec; Alternate Manufacturer: 3M; Value: 1x2
ZZ1 = CMP-0077238-1
ZZ2 = CMP-0077236-1
ZZ3 = CMP-0077237-1

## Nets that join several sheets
DVDD1: AMPS078A_PPCMB-IO (J2.1), AMPS078A_TAS5825MRSM (8 pins)
DVDD2: AMPS078A_PPCMB-IO (J3.1), AMPS078A_TAS5720MRSM (C15.1 R12.2 R13.2 U2.11)
GND: AMPS078A_PPCMB-IO (33 pins), AMPS078A_TAS5720MRSM (17 pins), AMPS078A_TAS5825MRSM (25 pins)
PVDD1: AMPS078A_PPCMB-IO (J1.2 TP1.1), AMPS078A_TAS5825MRSM (12 pins)
PVDD2: AMPS078A_PPCMB-IO (J10.2 TP2.1), AMPS078A_TAS5720MRSM (9 pins)
~{MUTE}: AMPS078A_PPCMB-IO (J5.78 TP10.1), AMPS078A_TAS5825MRSM (R10.1 U1.10)
~{PDN}: AMPS078A_PPCMB-IO (J5.90 R18.2), AMPS078A_TAS5720MRSM (R11.2), AMPS078A_TAS5825MRSM (R17.1 U1.17)
~{SPK_FAULT}: AMPS078A_PPCMB-IO (J5.22), AMPS078A_TAS5720MRSM (U2.2), AMPS078A_TAS5825MRSM (R9.1 U1.9)
LRCLK: AMPS078A_PPCMB-IO (J5.47 TP8.1), AMPS078A_TAS5720MRSM (U2.4), AMPS078A_TAS5825MRSM (U1.12)
MCLK: AMPS078A_PPCMB-IO (J5.41), AMPS078A_TAS5720MRSM (U2.5)
SCL: AMPS078A_PPCMB-IO (R5.1 R7.1 TP4.1), AMPS078A_TAS5720MRSM (U2.8), AMPS078A_TAS5825MRSM (U1.16)
SCLK: AMPS078A_PPCMB-IO (J5.45 TP7.1), AMPS078A_TAS5720MRSM (U2.6), AMPS078A_TAS5825MRSM (U1.13)
SDA: AMPS078A_PPCMB-IO (R6.1 R8.1 TP6.1), AMPS078A_TAS5720MRSM (U2.9), AMPS078A_TAS5825MRSM (U1.15)
SDIN: AMPS078A_PPCMB-IO (J5.49 TP9.1), AMPS078A_TAS5720MRSM (J9.3), AMPS078A_TAS5825MRSM (U1.14)
SDOUT: AMPS078A_PPCMB-IO (TP5.1), AMPS078A_TAS5720MRSM (J9.1), AMPS078A_TAS5825MRSM (R16.1 U1.11)

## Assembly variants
001: not fitted FID1 FID2 FID3 FID4 FID5 FID6 R12 R13 R20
